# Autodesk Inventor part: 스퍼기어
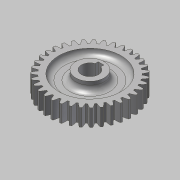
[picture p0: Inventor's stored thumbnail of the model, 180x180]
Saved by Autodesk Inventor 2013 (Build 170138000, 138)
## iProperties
Created: 2013-08
Part Number: 스퍼기어
Material: 강
Document SubType Name: Modeling
Designer: 한국산업디자인학원
Categories: <?xml version="1.0" encoding="UTF-16"?> <MemberInstance><Categories><FamilyTemplate><FamilyTemplateParameter ValueType="xs:double" Id="1" ObjectReferenceKey="da
Density: 1 g/cm^3
CustomPartVersion: 1
Author: 한국산업디자인학원
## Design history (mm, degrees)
sketch "Sketch1"
  geometry: C1 r 37 at (0, 0)
  constraints: 1 centre point
  dimensions: "d0" = 74 diameter of C1 (= da_da)
extrude "Extrusion1" new body sketch "Sketch1" distance "d1" = 15 (= da_b); taper "d2" = 0 deg
workplane "Work Plane2"
feature "피치 지름" dims "d4" = 10, "d5" = 0
workplane "Work Plane8"
workplane "Work Plane9"
feature "스퍼 기어" dims "da_b" = 15, "da_d" = 70, "da_aw" = 70, "da_da" = 74, "da_df" = 65, "da_dw" = 70, angle "da_beta" = 0 deg, "da_lefttooth" = 0, "da_righttooth" = 0
node "작업 평면11"
sketch "스케치3"
  geometry: C1 r 12.5 at (0, 0); 1 further point
  constraints: 1 centre point, 1 coincident
  dimensions: "d50" = 25 diameter of C1
extrude "돌출2" join sketch "스케치3" distance "d51" = 31; taper "d52" = 0 deg
sketch "스케치4"
  geometry: L1 (-2.5, 7.071)-(-2.5, 9.8); L2 (-2.5, 9.8)-(2.5, 9.8); L3 (2.5, 9.8)-(2.5, 7.071); C1 r 12.5 at (0, 0) reference; A1 r 7.5 centre (0, 0) between (-2.5, 7.071) and (2.5, 7.071); 1 further point
  constraints: 6 end point, 2 point on circle, 1 centre point, 1 coincident, 1 midpoint, 1 parallel, 1 perpendicular, 1 vertical, 1 vertical alignment
  dimensions: "d53" = 15 diameter of A1; "d54" = 5 distance of L1.end L2.end; "d55" = 17.3 dimension on A1 L2
extrude "돌출3" cut sketch "스케치4" distance "d56" = 31; taper "d57" = 0 deg
sketch "스케치5"
  geometry: C1 r 12.5 at (0, 0) reference; C2 r 27.5 at (0, 0); A1 r 32.5 centre (0, 0) between (9.347, 31.127) and (7.941, 31.515) reference
  constraints: 1 centre point, 1 coincident
  dimensions: "d58" = 55 diameter of C2
extrude "돌출4" cut sketch "스케치5" distance "d59" = 5; taper "d60" = 0 deg
sketch "스케치6"
  geometry: C1 r 12.5 at (0, 0) reference; C2 r 27.5 at (0, 0); A1 r 37 centre (0, 0) between (-5.788, 36.544) and (-7.422, 36.248) reference
  constraints: 1 centre point, 1 coincident
  dimensions: "d61" = 55 diameter of C2
extrude "돌출5" cut sketch "스케치6" distance "d62" = 5; taper "d63" = 0 deg
fillet "모깎기1" dims "d64" = 5
body "Solid1"
sketch "Sketch2"
  geometry: C1 r 37 at (0, 0) reference; C2 r 35 at (0, 0)
  constraints: 1 centre point, 1 coincident
  dimensions: "d3" = 70 diameter of C2 (= da_dw)
body "Srf1"
other parameters: "d17" = 0, "d34" = 0.8976 (computed from da_z), "d39" = 0, "d41" = 0, "d47" = 0, "d48" = 0, "d49" = 3
